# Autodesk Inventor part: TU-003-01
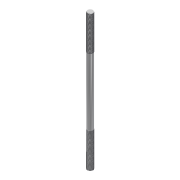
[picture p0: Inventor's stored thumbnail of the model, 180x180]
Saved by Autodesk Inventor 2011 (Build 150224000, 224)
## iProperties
Shininess: 64.0
Angle Display Precision: 2
Document Length Units: 11269
Document Angle Units: 11279
Document Time Units: 11290
Document Mass Units: 11283
Document Length Units Precision: 3
Document Angle Units Precision: 2
Compacted: True
Created: 2002-07
Part Number: TU-003-01
Document SubType Name: Modeling
Designer: PN
Description: Rod - 35 mm stroke length
Mass: 18.7131 g
Surface Area: 18.8805 cm^2
Volume: 2.31598 cm^3
Density: 8.08 g/cm^3
Material: Stainless Steel
Density: 0.0
Volumn: 0.0
Area: 0.0
PropertySet Name: Model Information
Control State: 0
Master: False
Checked Out: False
Author: PN
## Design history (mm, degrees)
sketch "Sketch1"
  geometry: C1 r 2.5 at (0, 0); 1 further point
  constraints: 1 centre point, 1 coincident
  dimensions: "d0" = 5 diameter of C1
extrude "Extrusion1" new body sketch "Sketch1" stored distance "d1" = 118 (computed from Stroke_Length); taper "d2" = 0 deg
chamfer "Chamfer1" distance "d3" = 0.25; stored, may be unused: second distance "d4" = 0.25, angle "d7" = 45 deg
thread "Thread1" dims "d5" = 30, "d6" = 0
thread "Thread2" dims "d8" = 30, "d9" = 0
body "Solid1"
other parameters: "Stroke_Length" = 35 [user parameter; used in 1 equation term]
